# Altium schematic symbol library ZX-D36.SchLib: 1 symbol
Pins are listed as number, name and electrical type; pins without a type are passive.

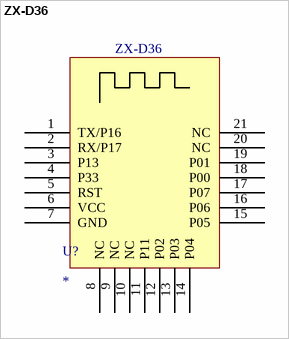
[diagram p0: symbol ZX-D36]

## ZX-D36
designator U?
footprint ZX-D36 (Footprint not found)
pins: 1 TX/P16 "串口输出/TXD", 2 RX/P17 "串口输入/RXD", 3 P13 "定制输入输出引脚", 4 P33 "定制输入输出引脚", 5 RST "定制输入输出引脚", 6 VCC (power) "电源 (2- 3.6V)", 7 GND (power) "地", 8 NC "悬空", 9 NC "悬空", 10 NC "悬空", 11 P11 "LED 灯引脚", 12 P02 "按键脚", 13 P03 "STATE 状态脚", 14 P04 "AT指令选择引脚", 15 P05 "低功耗控制引脚", 16 P06 "定制输入输出引脚", 17 P07 "定制输入输出引脚", 18 P00 "定制输入输出引脚", 19 P01 "定制输入输出引脚", 20 NC "悬空", 21 NC "悬空"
